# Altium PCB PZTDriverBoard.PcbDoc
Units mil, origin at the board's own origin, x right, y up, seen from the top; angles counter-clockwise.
Board outline 2900 x 7500 mil, 6 copper layers (Top Layer, GND1, P15, N15, GND2, Bottom Layer); 146 components, 71 nets, 417 pads, 78 vias.
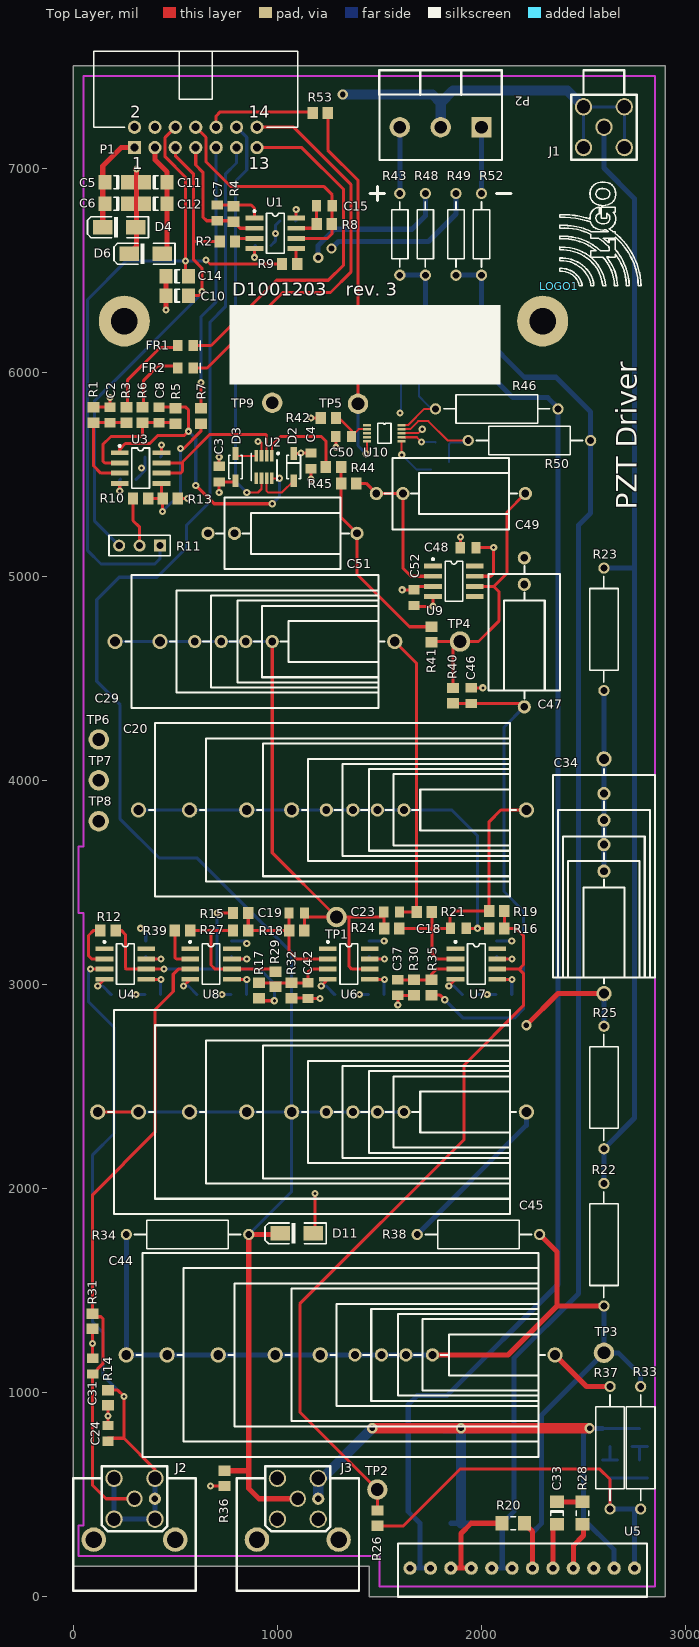
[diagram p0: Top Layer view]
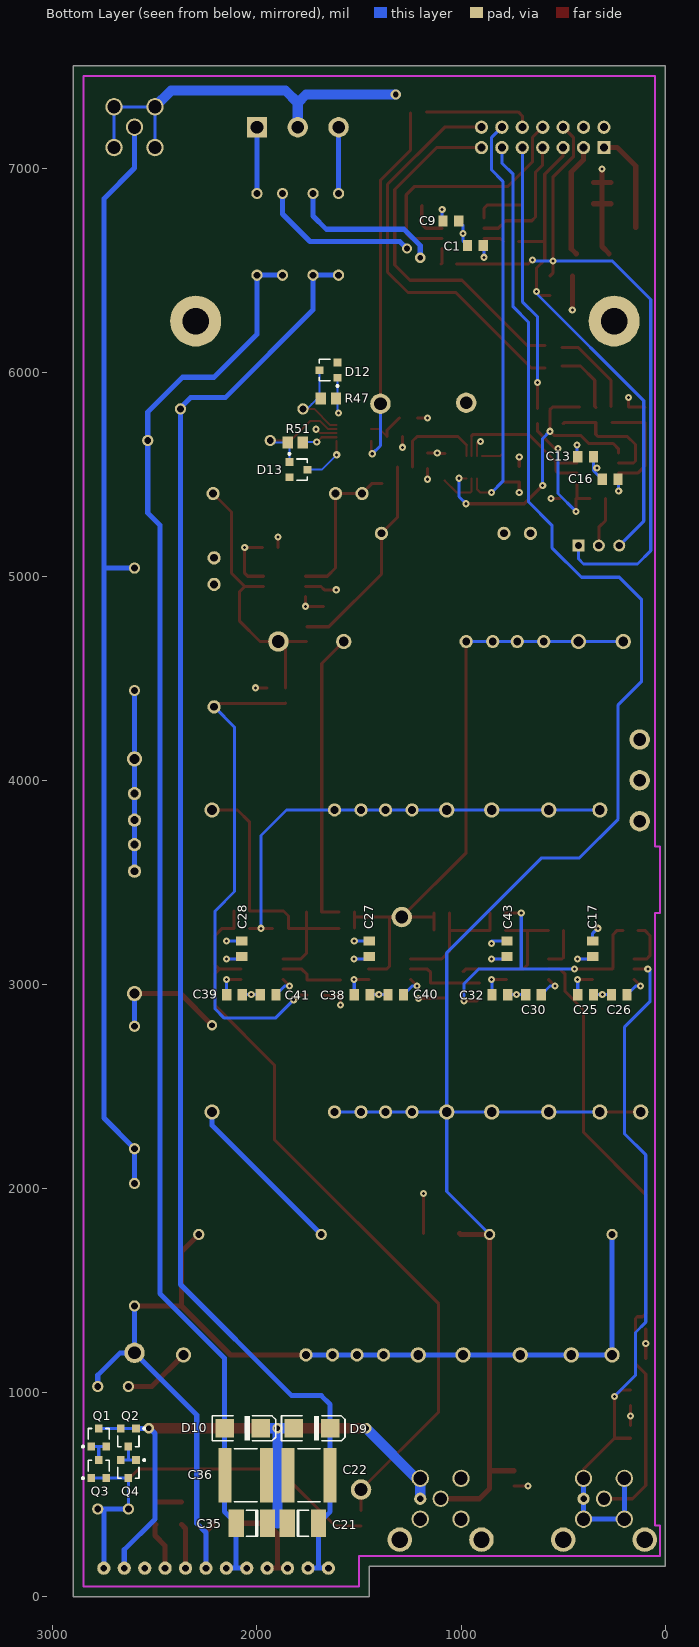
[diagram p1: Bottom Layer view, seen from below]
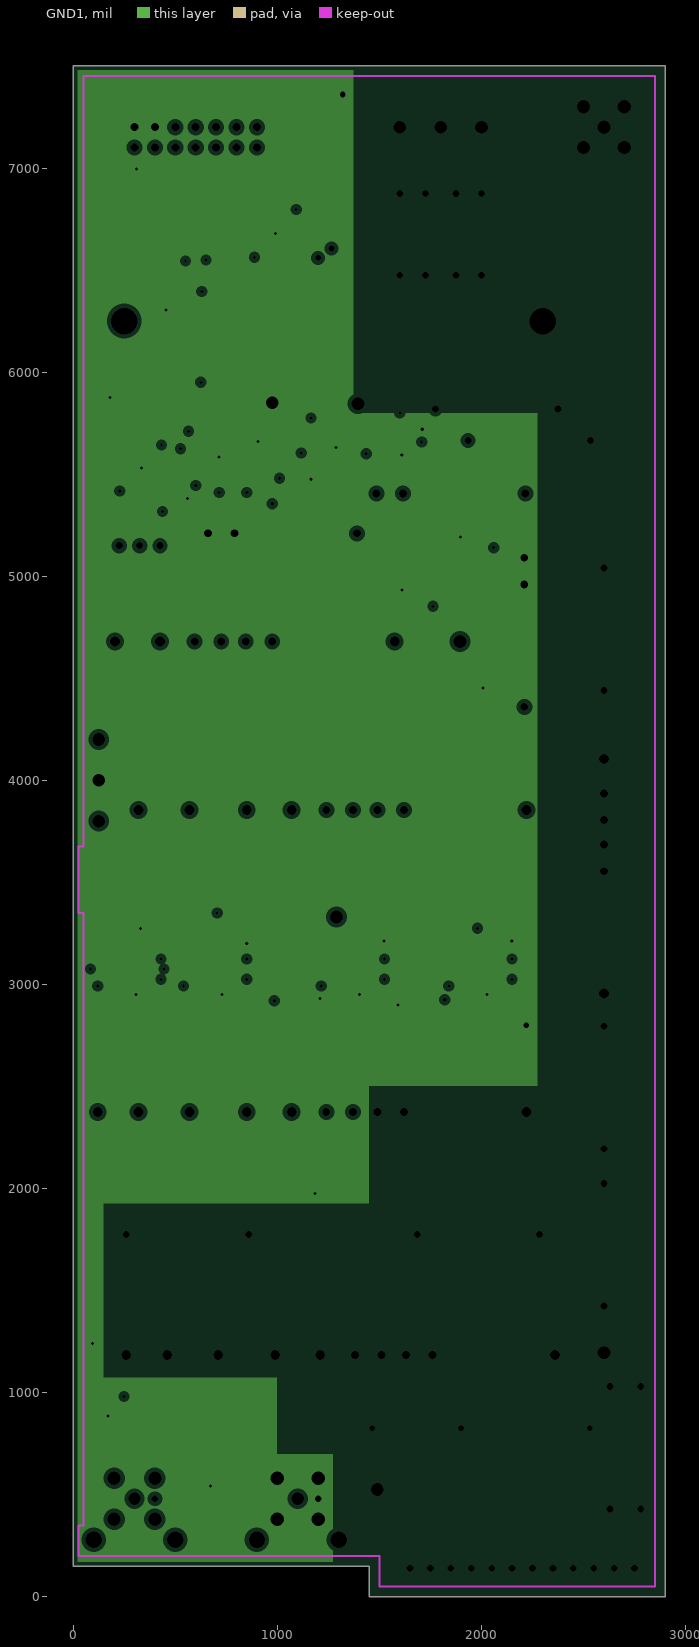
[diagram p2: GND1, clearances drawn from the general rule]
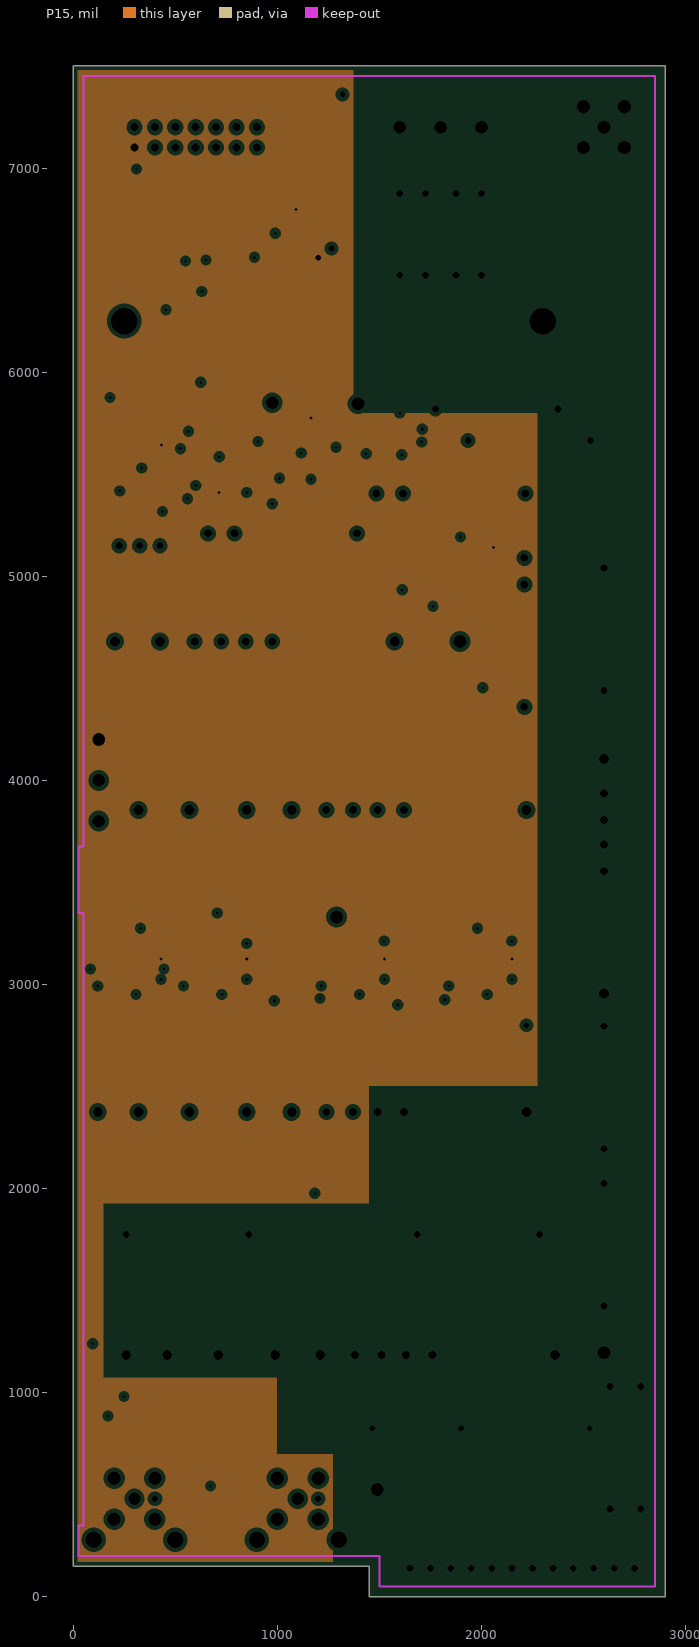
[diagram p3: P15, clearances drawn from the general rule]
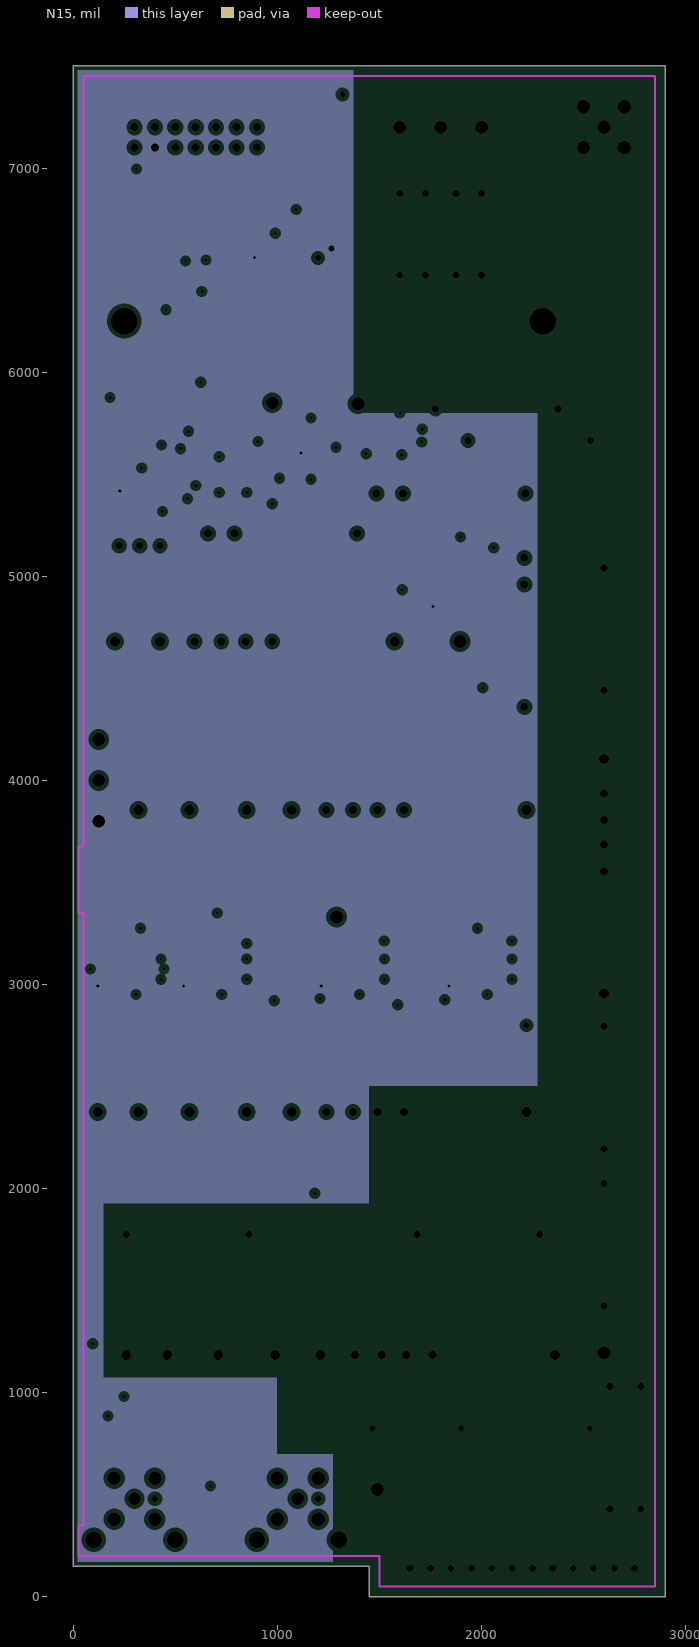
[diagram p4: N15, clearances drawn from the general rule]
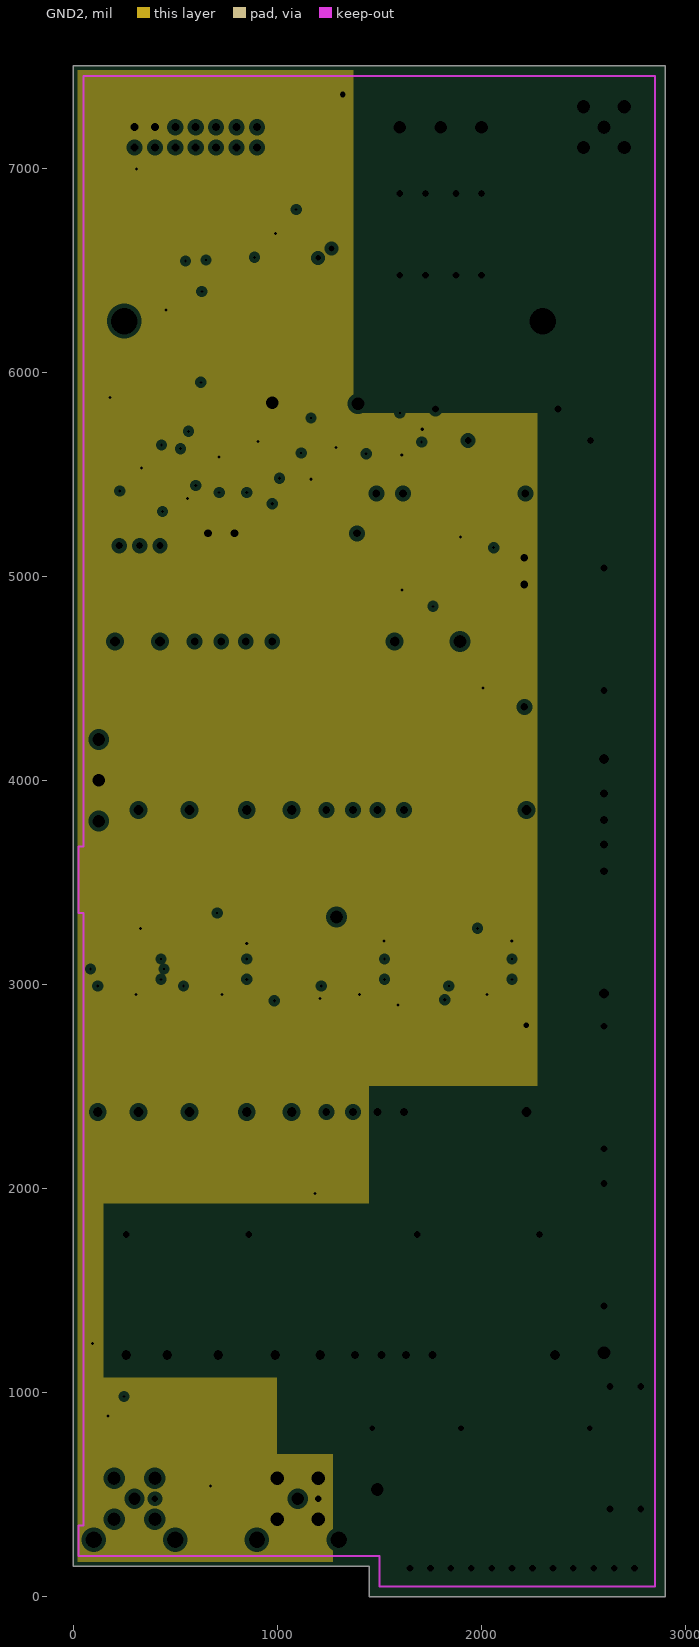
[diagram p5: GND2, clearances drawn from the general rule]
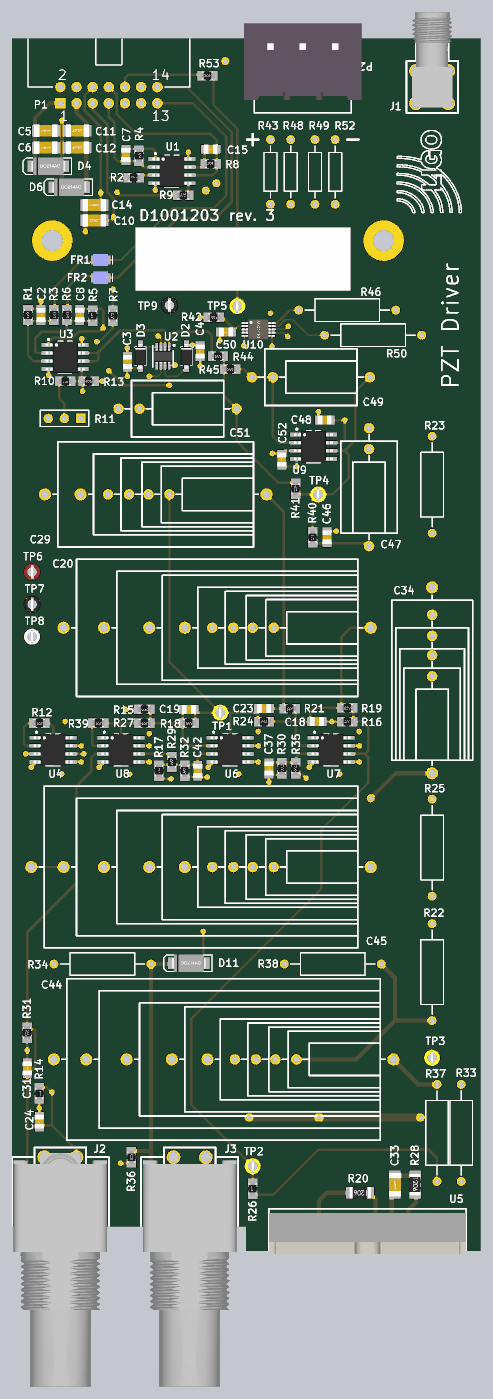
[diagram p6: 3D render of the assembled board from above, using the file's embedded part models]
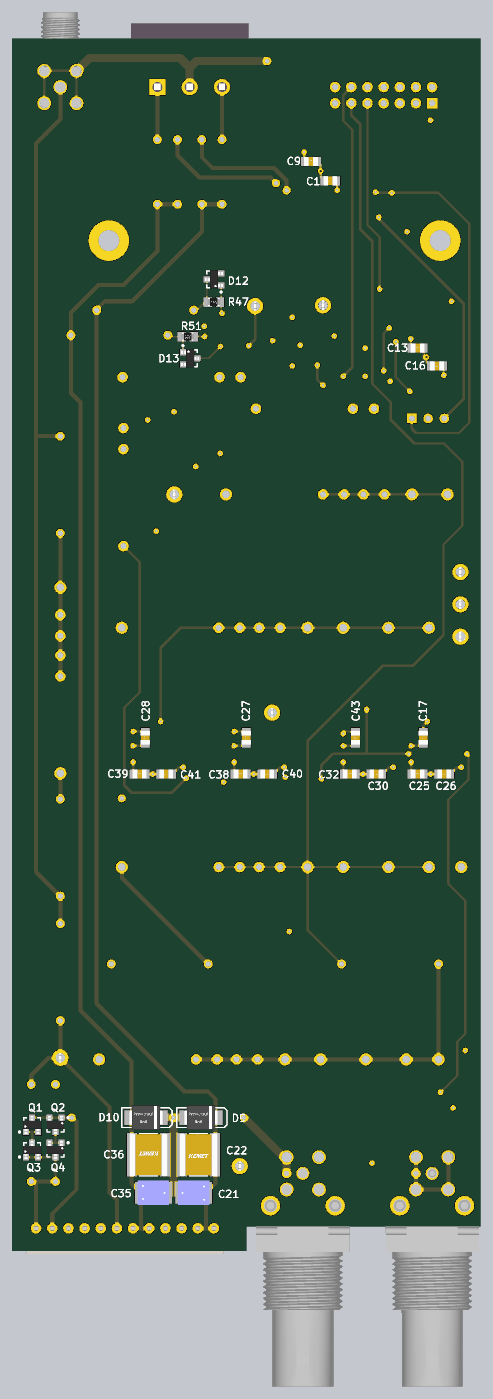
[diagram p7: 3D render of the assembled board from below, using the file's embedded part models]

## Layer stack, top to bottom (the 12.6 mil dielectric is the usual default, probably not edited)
Top Solder: solder mask 0.4, Solder Resist, Dk 3.5
Top Layer: signal copper 1.4
Dielectric1: core 12.6, FR-4, Dk 4.8
GND1: plane copper 1.4
Dielectric2: prepreg 12.6, FR-4, Dk 4.8
P15: plane copper 1.4
Dielectric3: core 12.6, FR-4, Dk 4.8
N15: plane copper 1.4
Dielectric4: prepreg 12.6, FR-4, Dk 4.8
GND2: plane copper 1.4
Dielectric5: core 12.6, FR-4, Dk 4.8
Bottom Layer: signal copper 1.4
Bottom Solder: solder mask 0.4, Solder Resist, Dk 3.5

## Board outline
0,150 0,7500 2900,7500 2900,0 1450,0 1450,150

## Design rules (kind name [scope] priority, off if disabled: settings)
Clearance Clearance_MSOP [(HasFootprint('MSOP10'))] p1: gap=8 ignorepadtopadclearanceinfootprint=FALSE
Clearance Clearance_HV [(InNet('N') OR InNet('P') OR InNet('PHV') OR InNet('NHV') OR InNet('HVFB') OR InNet('HVOUT'))] p2: gap=35 ignorepadtopadclearanceinfootprint=FALSE
Clearance [All] p3: gap=8 ignorepadtopadclearanceinfootprint=FALSE
Height [All] p1: minheight=0 maxheight=1200 prefheight=500
HoleSize [All] p1: absolutevalues=TRUE maxlimit=250 minlimit=15 maxpercent=80.000 minpercent=20.000
MinimumSolderMaskSliver [All] p1: minsoldermaskwidth=0
PlaneClearance [All] p1: clearance=20
PlaneConnect [All] p1: planeconnectstyle=Relief reliefexpansion=20 reliefentries=4 reliefconductorwidth=10 reliefairgap=10
PolygonConnect [All] p1: connectstyle=Relief reliefconductorwidth=10 reliefentries=4 polygonreliefangle="90 Angle" airgapwidth=10
RoutingVias [All] p1: holewidth=15 width=35 viastyle="Through Hole" minholewidth=15 minwidth=35 maxholewidth=28 maxwidth=50
SilkToSilkClearance [All] p1: silktosilkclearance=0
SilkToSolderMaskClearance SilkscreenOverComponentPads [IsPad] p1: minsilkscreentomaskgap=0 clearancetoexposedcopper=TRUE
SolderMaskExpansion [All] p1: expansion=4 istentingtop=FALSE
SupplyNets "Schematic Supply Nets_8" [InNet('VREF')] p1: voltage=0.000
SupplyNets "Schematic Supply Nets_7" [InNet('GND')] p2: voltage=0.000
SupplyNets "Schematic Supply Nets_6" [InNet('P15')] p3: voltage=0.000
SupplyNets "Schematic Supply Nets_5" [InNet('PHV')] p4: voltage=0.000
SupplyNets "Schematic Supply Nets_4" [InNet('NHV')] p5: voltage=0.000
SupplyNets "Schematic Supply Nets_3" [InNet('P')] p6: voltage=0.000
SupplyNets "Schematic Supply Nets_2" [InNet('N15')] p7: voltage=0.000
SupplyNets "Schematic Supply Nets_1" [InNet('N')] p8: voltage=0.000
SupplyNets "Schematic Supply Nets" [InNet('NREF')] p9: voltage=0.000
Width [All] p1: maxlimit=100 minlimit=8 preferedwidth=12
23 further rules are at their usual default settings.

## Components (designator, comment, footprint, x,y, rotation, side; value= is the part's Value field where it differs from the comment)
C1 "100n" CC2013-0805 930,6620 r180 bottom
C2 "1n" CC2013-0805 180,5790 r90 top
C3 "100n" CC2013-0805 715,5500 r270 top
C4 "100n" CC2013-0805 1165,5565 r270 top
C5 "100n" CC3216-1206 210,6930 r180 top
C6 "10u" CC3216-1206 210,6825 r180 top
C7 "1n" CC2013-0805 705,6780 r90 top
C8 "1n" CC2013-0805 420,5790 r90 top
C9 "100n" CC2013-0805 1050,6740 r0 bottom
C10 "100n" CC3216-1206 510,6375 r0 top
C11 "100n" CC3216-1206 405,6930 r0 top
C12 "10u" CC3216-1206 405,6825 r0 top
C13 "100n" CC2013-0805 390,5585 r0 bottom
C14 "100n" CC3216-1206 510,6470 r0 top
C15 "1n" CC2013-0805 1230,6815 r180 top
C16 "100n" CC2013-0805 270,5475 r180 bottom
C17 "100n" CC2013-0805 355,3175 r270 bottom
C18 "1n" CC2013-0805 1886.61,3275 r0 top
C19 "10p" CC2013-0805 1095,3350 r180 top
C20 "NL" CA-ALL8 2220,3855 r180 top
C21 "100n" CL4532-1812 1775,360 r180 bottom
C22 "1u" CC5664-2225 1745,595 r180 bottom
C23 "1n" CC2013-0805 1560,3355 r180 top
C24 "NL" CC2013-0805 170,800 r270 top
C25 "68p" CC2013-0805 390,2950 r0 bottom
C26 "100n" CC2013-0805 225,2950 r180 bottom
C27 "100n" CC2013-0805 1450,3175 r270 bottom
C28 "100n" CC2013-0805 2075,3175 r270 bottom
C29 "NL" CA-ALL6 1575,4680 r180 top
C30 "100n" CC2013-0805 645,2950 r180 bottom
C31 "NL" CC2013-0805 95,1130 r90 top
C32 "68p" CC2013-0805 810,2950 r0 bottom
C33 "68p" CC3216-1206 2370,410 r270 top
C34 "470n" CA-ALL5 2600,2955 r90 top value=270n
C35 "100n" CL4532-1812 2025,360 r0 bottom
C36 "1u" CC5664-2225 2055,595 r0 bottom
C37 "1n" CC2013-0805 1590,2985 r90 top
C38 "68p" CC2013-0805 1485,2950 r0 bottom
C39 "68p" CC2013-0805 2110,2950 r0 bottom
C40 "100n" CC2013-0805 1320,2950 r180 bottom
C41 "100n" CC2013-0805 1945,2950 r180 bottom
C42 "10p" CC2013-0805 1150,2970 r90 top
C43 "100n" CC2013-0805 775,3175 r270 bottom
C44 "1u" CA-ALL9 2360,1185 r180 top value=560n
C45 "1u" CA-ALL9 2220,2375 r180 top value=560n
C46 "1n" CC2013-0805 1950,4415 r90 top
C47 "1u" CA-ALL2 2210,4360 r90 top
C48 "100n" CC2013-0805 1935,5140 r0 top
C49 "330n" CA-ALL2 2215,5405 r180 top
C50 "100n" CC2013-0805 1325,5685 r0 top
C51 "1u" CA-ALL2 1390,5210 r180 top
C52 "100n" CC2013-0805 1670,4895 r270 top
D2 "DIODE" DO-SOD123 1080,5535 r90 top
D3 "DIODE" DO-SOD123 795,5535 r90 top
D4 "shottky diode" DO-SMA 225,6710 r180 top
D6 "shottky diode" DO-SMA 355,6580 r180 top
D9 "zener diode" DO-SMB 1730,825 r180 bottom
D10 "zener diode" DO-SMB 2070,825 r180 bottom
D11 "zener diode" DO-SMA 1095,1780 r180 top
D12 "Zener diode" SO-G3/C2.25 1650,6010 r90 bottom
D13 "Zener diode" SO-G3/C2.25 1797,5522 r270 bottom
FR1 "MPZ1608D300B" CL2013-0805 550,6130 r180 top
FR2 "MPZ1608D300B" CL2013-0805 550,6020 r180 top
J1 "SMA" SMA-RA 2600,7200 r180 top
J2 "SMA" SMA_BNC_VARIANT 300,20 r180 top
J2 "TNC" BNC_SMA 300,20 r180 top locked
J3 "BNC" BNC_SMA 1100,20 r180 top
LOGO1 "LIGO logo" LIGO_LOGO 2380,6420 r90 top
P1 "09 18 514 7323" 918514x323 600,7200 r0 top
P2 "TBlock_5.08_3" TBLOCK-5.08-3 1800,7200 r180 top
Q1 "MMBF4416A" SO-G3/C2.25 2775,780 r180 bottom
Q2 "MMBF4416A" SO-G3/C2.25 2630,780 r0 bottom
Q3 "MMBF4416A" SO-G3/C2.25 2775,625 r180 bottom
Q4 "MMBF4416A" SO-G3/C2.25 2630,625 r0 bottom
R1 "10K" CR2012-0805 100,5790 r90 top
R2 "4.99K" CR2012-0805 755,6640 r0 top
R3 "10K" CR2012-0805 260,5790 r270 top
R4 "100" CR2012-0805 785,6775 r270 top
R5 "10K" CR2012-0805 500,5785 r90 top
R6 "10K" CR2012-0805 340,5790 r270 top
R7 "49.9K" CR2012-0805 625,5785 r90 top
R8 "100" CR2012-0805 1230,6725 r0 top
R9 "4.99K" CR2012-0805 1060,6530 r0 top
R10 "49.9K" CR2012-0805 330,5380 r180 top
R11 "10K" HDR1X3 425,5150 r180 top
R12 "100" CR2012-0805 170,3265 r180 top
R13 "1M" CR2012-0805 475,5380 r180 top
R14 "1M" CR2012-0805 170,975 r270 top
R15 "4.99K" CR2012-0805 820,3350 r180 top
R16 "NL" CR2012-0805 2075,3275 r180 top
R17 "NL" CR2012-0805 910,2970 r270 top
R18 "4.99K" CR2012-0805 1095,3265 r180 top
R19 "4.99K" CR2012-0805 2075,3360 r180 top
R20 "20" CR3216-1206 2155,360 r180 top
R21 "NL" CR2012-0805 1720,3355 r180 top
R22 "499" AXIAL-0.6 2600,1725 r90 top
R23 "0" AXIAL-0.6 2600,4740 r90 top
R24 "4.99K" CR2012-0805 1560,3275 r180 top
R25 "NL" AXIAL-0.6 2600,2495 r270 top
R26 "12K" CR2012-0805 1490,385 r90 top
R27 "NL" CR2012-0805 820,3265 r180 top
R28 "100" CR3216-1206 2495,410 r270 top
R29 "4.99K" CR2012-0805 990,3025 r90 top
R30 "49.9K" CR2012-0805 1670,2985 r270 top
R31 "1M" CR2012-0805 95,1350 r90 top
R32 "4.99K" CR2012-0805 1070,2970 r90 top
R33 "150K" AXIAL-0.6 2780,730 r90 top value=240K
R34 "150K" AXIAL-0.6 560,1775 r0 top value=240K
R35 "0" CR2012-0805 1755,2985 r270 top
R36 "12K" CR2012-0805 740,580 r90 top
R37 "16.9K" AXIAL-0.6 2630,730 r90 top value=26.7K
R38 "16.9K" AXIAL-0.6 1985,1775 r180 top value=26.7K
R39 "100" CR2012-0805 535,3265 r180 top
R40 "49.9K" CR2012-0805 1860,4415 r270 top
R41 "49.9K" CR2012-0805 1755,4715 r270 top
R42 "10K" CR2012-0805 1250,5775 r180 top
R43 "0" AXIAL-0.4 1600,6675 r270 top
R44 "49.9K" CR2012-0805 1275,5535 r180 top
R45 "49.9K" CR2012-0805 1350,5455 r180 top
R46 "1M" AXIAL-0.6 2075,5820 r180 top
R47 "4.99K" CR2012-0805 1650,5870 r0 bottom value=2.94K
R48 "0" AXIAL-0.4 1725,6675 r270 top
R49 "0" AXIAL-0.4 1875,6675 r270 top
R50 "1M" AXIAL-0.6 2235,5665 r180 top
R51 "49.9K" CR2012-0805 1812,5656 r0 bottom value=4.99K
R52 "0" AXIAL-0.4 2000,6675 r270 top
R53 "0" CR2012-0805 1210,7270 r0 top
TP1 "Testpoint" TP1-YLW 1290,3330 r0 top
TP2 "Testpoint" TP1-YLW 1490,525 r0 top
TP3 "Testpoint" TP1-YLW 2600,1195 r0 top
TP4 "Testpoint" TP1-YLW 1895,4680 r0 top
TP5 "Testpoint" TP1-YLW 1395,5845 r0 top
TP6 "Testpoint" TP1-RED 125,4200 r0 top
TP7 "Testpoint" TP1-BLK 125,4000 r0 top
TP8 "Testpoint" TP1-WHT 125,3800 r0 top
TP9 "Testpoint" TP1-BLK 975,5850 r0 top
U1 "AD8672AR" SO-G8 990,6680 r270 top
U2 "MAX4649" SSO-G8/NARROW 935,5535 r180 top
U3 "AD8672AR" SO-G8 330,5530 r270 top
U4 "AD829JR" SO-G8 255,3100 r270 top
U5 "PA90" PA98 2750,140 r180 top locked
U6 "AD829JR" SO-G8 1350,3100 r270 top
U7 "AD829JR" SO-G8 1975,3100 r270 top
U8 "AD829JR" SO-G8 675,3100 r270 top
U9 "OP27" SO-G8 1865,4975 r270 top
U10 "LTC2919" MSOP10 1440,5740 r0 top

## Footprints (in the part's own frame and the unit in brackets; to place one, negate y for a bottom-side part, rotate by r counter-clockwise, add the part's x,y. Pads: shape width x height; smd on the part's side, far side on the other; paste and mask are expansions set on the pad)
918514x323 [mm] "Connector; IDC, Low Profile Male Header, Thru-Hole; 14 Position; Right Angle; Pitch 2.54 mm; Body 25.40 x 8.9 x 9.2 mm (LxWxH)"
  rect 1.65x1.65 hole 1: 1(-7.62,-2.54)
  round 1.65 hole 1: 2(-7.62,0) 3(-5.08,-2.54) 4(-5.08,0) 5(-2.54,-2.54) 6(-2.54,0) 7(0,-2.54) 8(0,0) 9(2.54,-2.54) 10(2.54,0) 11(5.08,-2.54) 12(5.08,0) 13(7.62,-2.54) 14(7.62,0)
  silkscreen extent -12.7,0 12.7,9.45
AXIAL-0.4 [mm] "Axial Device, Thru-Hole; 2 Leads; 0.4 in Pin Spacing"
  round 1.4 hole 0.85: 1(-5.08,0) 2(5.08,0)
  silkscreen extent -4.06,-1.02 4.06,1.02, body extent -3.05,-1.14 3.05,1.14, height 2.35
AXIAL-0.6 [mm] "Axial Device, Thru-Hole; 2 Leads; 0.6 in Pin Spacing"
  round 1.4 hole 0.85: 1(-7.62,0) 2(7.62,0)
  silkscreen extent -6.6,-1.78 6.6,1.78, body extent -5.08,-1.83 5.08,1.83, height 3.73
BNC_SMA [mil] "BNC right angle PCB with alternative SMA footprint"
  round 80 hole 60: 1(0,-460)
  round 85 hole 65: 2(-100,-360) 2(-100,-560) 2(100,-360) 2(100,-560)
  round 60 hole 32: 2(-100,-460)
  round 120 hole 80: 3(-200,-260) 4(200,-260)
  silkscreen extent -300,-620 300,-10, body extent -289,-540 289,858, height 623
CA-ALL2 [mil] "Axial film capacitor, Size up to 0.53\"(L) x 0.35\"(D)"
  round 65 hole 38: 1(0,0) 2(600,0) 2(730,0)
  silkscreen extent 40,-175 690,175, body extent 80,-175 650,175, height 360
CA-ALL5 [mil] "Axial film capacitor, Size up to 0.95\"(L) x 0.5\"(D)"
  round 75 hole 48: 1(0,0) 2(1150,0)
  round 65 hole 38: 2(600,0) 2(730,0) 2(850,0) 2(980,0)
  silkscreen extent 50,-250 1100,250, body extent 80,-250 1070,250, height 510
CA-ALL6 [mil] "Axial film capacitor, Size up to 1.17\"(L) x 0.65\"(D)"
  round 75 hole 48: 1(0,0) 2(1150,0) 2(1370,0)
  round 65 hole 38: 2(600,0) 2(730,0) 2(850,0) 2(980,0)
  silkscreen extent 50,-325 1320,325, body extent 80,-325 1290,325, height 660
CA-ALL8 [mil] "Axial film capacitor, Size up to 1.68\"(L) x 0.85\"(D)"
  round 75 hole 48: 1(0,0) 2(1150,0) 2(1370,0) 2(1650,0) 2(1900,0)
  round 65 hole 38: 2(600,0) 2(730,0) 2(850,0) 2(980,0)
  silkscreen extent 50,-425 1850,425, body extent 80,-425 1820,425, height 860
CA-ALL9 [mil] "Axial film capacitor, Size up to 1.9\"(L) x 1.0\"(D)"
  round 75 hole 48: 1(0,0) 2(1150,0) 2(1370,0) 2(1650,0) 2(1900,0) 2(2100,0)
  round 65 hole 38: 2(600,0) 2(730,0) 2(850,0) 2(980,0)
  silkscreen extent 50,-500 2050,500, body extent 80,-500 2020,500, height 1010
CC2013-0805 [mm] "Chip Capacitor; Body 2.0 x 1.3 mm (LxW typ)"
  rect 1.15x1.4 smd: 1(-0.975,0) 2(0.975,0)
  body extent -1.1,-0.73 1.1,0.72, height 0.88
CC3216-1206 [mm] "Chip Capacitor; Body 3.2 x 1.6 mm (LxW typ)"
  rect 1.6x1.8 smd: 1(-1.4,0) 2(1.4,0)
  silkscreen extent -0.3,-0.8 0.3,0.8, body extent -1.85,-0.97 1.85,0.97, height 0.88
CC5664-2225 [mm] "Chip Capacitor, Body 5.6 x 6.4mm (LxW typ)"
  rect 1.6x6.8 smd: 1(-2.6,0) 2(2.6,0)
  silkscreen extent -1.4,-3.3 1.4,3.3, body extent -3,-3.4 3,3.4, height 1.55
CL2013-0805 [mm] "Chip Inductor; Body 2.0 x 1.3 mm (LxW typ)"
  rect 1.15x1.4 smd: 1(-0.975,0) 2(0.975,0)
  silkscreen extent -1.85,-0.6 -1.85,0.6, body extent -1.15,-0.95 1.14,0.96, height 1.59
CL4532-1812 [mm] "Chip Inductor; Body 4.5 x 3.2 mm (LxW typ)"
  rect 1.9x3.4 smd: 1(-1.95,0) 2(1.95,0)
  silkscreen extent -0.7,-1.6 0.7,1.6, body extent -2.47,-1.91 2.47,1.91, height 3.42
CR2012-0805 [mm] "Chip Resistor; Body 2.0 x 1.3 mm (LxW typ)"
  rect 1.3x1.5 smd: 1(-0.95,0) 2(0.95,0)
  body extent -1,-0.62 1,0.63, height 0.46
CR3216-1206 [mm] "Chip Resistor; Body 3.2 x 1.6 mm (LxW typ)"
  rect 1.6x1.8 smd: 1(-1.4,0) 2(1.4,0)
  silkscreen extent -0.3,-0.8 0.3,0.8, body extent -1.67,-0.86 1.68,0.87, height 0.85
DO-SMA [mm] "DO-214-AC/SMA; 2 C-Bend Leads; Body 5 x 2.7 mm, inc. leads (LxW)"
  rect 2.4x1.8 smd: 1(-2.05,0) 2(2.05,0)
  silkscreen extent -3.65,-1.3 3.95,1.3, body extent -2.74,-1.4 2.74,1.4, height 2.41
DO-SMB [mm] "DO-214-AA/SMB; 2 C-Bend Leads; Body 5.3 x 3.6 mm, inc. leads (LxW)"
  rect 2.3x2.3 smd: 1(-2.25,0) 2(2.25,0)
  silkscreen extent -3.8,-1.55 4.1,1.55, body extent -2.75,-1.95 2.75,1.95, height 2.45
DO-SOD123 [mm] "SOD-123; 2 Leads; Body 2.7 x 1.6 mm, (LxW)"
  rect 1.6x0.8 smd: 1(-1.7,0) 2(1.7,0)
  silkscreen extent -1.45,-0.85 1.45,0.85, body extent -1.95,-0.9 1.95,0.9, height 1.18
HDR1X3 [mm] "Connector; Header; 3 Position"
  rect 1.5x1.5 hole 0.9: 1(0,0)
  round 1.5 hole 0.9: 2(2.54,0) 3(5.08,0)
  silkscreen extent -1.27,-1.27 6.35,1.27
LIGO_LOGO [mil] "LIGO logo"
  silkscreen extent 3,-402 511,-3
MSOP10 [mm] "MSOP Plastic Small-Outline Package"
  rect 1x0.297 smd: 1(0,0) 2(0,-0.5) 3(0,-1) 4(0,-1.5) 5(0,-2) 6(4.3,-2) 7(4.3,-1.5) 8(4.3,-1) 9(4.3,-0.5) 10(4.3,0)
  silkscreen extent 1.33,-2.25 2.97,0.25, body extent -0.44,-2.59 4.71,0.61, height 1.09
PA98 [mil] "12-pin SIP package"
  round 65 hole 33: 1(0,0) 2(100,0) 3(200,0) 4(300,0) 5(400,0) 6(500,0) 7(600,0) 8(700,0) 9(800,0) 10(900,0) 11(1000,0) 12(1100,0)
  silkscreen extent -60,-120 1160,140, body extent -60,-95 1160,158, height 1017
SMA-RA [mil] "SMA right angle PCB"
  round 85 hole 65: 1(0,0) 2(-100,100) 2(-100,-100) 2(100,100) 2(100,-100)
  silkscreen extent -160,-160 160,160, body extent -125,-460 125,125, height 375
SMA_BNC_VARIANT [mil] "SMA straight PCB with alternative BNC footprint (3D-body only)"
  body extent -126,-586 126,-334, height 370
SO-G3/C2.25 [mm] "SOT-23; 3 Leads; Body 3.0 x 2.5 mm, inc. leads (LxW max)"
  rect 0.95x1 smd: 1(-0.95,-1.125) 2(0.95,-1.125) 3(0,1.125)
  silkscreen extent -2.1,-1.25 1.32,1.13, body extent -1.45,-1.4 1.45,1.4, height 1.3
SO-G8 [mm] "Small Outline; 8 Leads; Body Width 3.9 mm; Pitch 1.27 mm"
  rect 0.6x2.2 smd: 1(-1.905,-2.6) 2(-0.635,-2.6) 3(0.635,-2.6) 4(1.905,-2.6) 5(1.905,2.6) 6(0.635,2.6) 7(-0.635,2.6) 8(-1.905,2.6)
  silkscreen extent -2.88,-2.72 2.5,1.1, body extent -2.47,-3.06 2.47,3.06, height 1.75
SSO-G8/NARROW [mm] "SSOP narrow; 8 Leads; Body Width 1.7 mm; Pitch 0.65 mm"
  rect 0.445x1.4 smd: 1(-0.975,-1.4) 2(-0.325,-1.4) 3(0.325,-1.4) 4(0.975,-1.4) 5(0.975,1.4) 6(0.325,1.4) 7(-0.325,1.4) 8(-0.975,1.4)
  silkscreen extent -1.88,-1.82 1.6,1.7, body extent -1.5,-1.5 1.5,1.5, height 1.45
TBLOCK-5.08-3 [mil] "Terminal Block, 5.08mm, 3pin"
  rect 100x100 hole 62: 1(-200,0)
  round 100 hole 62: 2(0,0) 3(200,0)
  silkscreen extent -300,-160 300,160, body extent -363,-393 363,80, height 334
TP1-BLK [mm] "Testpoint pin, black"
  round 2.54 hole 1.58: 1(0,0)
  body extent -1.27,-1.27 1.27,1.27, height 4.89
TP1-RED [mm] "Testpoint pin, red"
  round 2.54 hole 1.58: 1(0,0)
  body extent -1.27,-1.27 1.27,1.27, height 4.89
TP1-WHT [mm] "Testpoint pin, white"
  round 2.54 hole 1.58: 1(0,0)
  body extent -1.27,-1.27 1.27,1.27, height 4.89
TP1-YLW [mm] "Testpoint pin, yellow"
  round 2.54 hole 1.58: 1(0,0)
  body extent -1.27,-1.27 1.27,1.27, height 4.89

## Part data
C1 C3 C4 C9 C13 C16 C17 C26 C27 C28 C30 C40 C41 C43 C48 C50 C52: library part ChipCap, "Capacitor, surface mount", Part Number=311-1140-1-ND, Tolerance=10%
C2 C7 C8 C15 C18 C23 C37 C46: library part ChipCap, "Capacitor, surface mount", Part Number=399-C0805C102J5GACTUCT-ND, Tolerance=10%
C5 C10 C11 C14: library part ChipCap, "Capacitor, surface mount", Part Number=311-1179-1-ND, Tolerance=10%
C6 C12: library part ChipCap, "Capacitor, surface mount", Part Number=1276-6767-1-ND, Tolerance=10%
C19 C42: library part ChipCap, "Capacitor, surface mount", Part Number=311-1099-1-ND, Tolerance=10%
C20 C29: library part CapFilmAxial, "Film Capacitor, axial lead", Tolerance=1%, Voltage Rating=50V
C21 C35: library part ChipCap, "Capacitor, surface mount", Part Number=490-16695-1-ND, Tolerance=10%, Voltage Rating=630V
C22 C36: library part ChipCap, "Capacitor, surface mount", Part Number=490-GRM43DR7LV224KW01LCT-ND, Tolerance=10%, Voltage Rating=630V
C24 C31: library part ChipCap, "Capacitor, surface mount", Tolerance=10%
C25 C32 C38 C39: library part ChipCap, "Capacitor, surface mount", Part Number=311-1109-1-ND, Tolerance=10%
C33: library part ChipCap, "Capacitor, surface mount", Part Number=490-4300-1-ND, Tolerance=10%, Voltage Rating=630V
C34: library part CapFilmAxial, "Film Capacitor, axial lead", Part Number=P12243-ND, Tolerance=5%, Voltage Rating=630V
C44 C45: library part CapFilmAxial, "Film Capacitor, axial lead", Part Number=2870-MKP1839456634HQ-ND, Tolerance=1%, Voltage Rating=630V
C47 C51: library part CapFilmAxial, "Film Capacitor, axial lead", Part Number=MU12B105F, Supplier Part Number 1=PCF1616-ND, Tolerance=1%, Voltage Rating=50V
C49: library part CapFilmAxial, "Film Capacitor, axial lead", Part Number=MU12B334F, Supplier Part Number 1=P122561-ND, Tolerance=1%, Voltage Rating=50V
D2 D3: "Single diode", Part Number=B0530W-FDICT-ND, Voltage Rating=30V
D4 D6: library part DIODE_SHOTTKY, "Single shottky diode", Part Number=641-1702-1-ND, Voltage Rating=40V
D9: library part DIODE_ZENER, "Single zener diode", Part Number=SMBJ200ALFCT-ND, Voltage Rating=200V
D10: library part DIODE_ZENER, "Single zener diode", Part Number=SMBJ120ALFCT-ND, Voltage Rating=120V
D11: library part DIODE_ZENER, "TVS", Part Number=576-SMAJ20CA, Voltage Rating=20V
D12 D13: library part DIODE_ZENER_SOT23, "Single zener diode in SOT23 package", Part Number=MMBZ5229BLT1GOSCT-ND, Voltage Rating=4.3V
FR1 FR2: library part BLM31PG121SN1, "ferrite bead, 20Ohm at 1GHz, 603", Part Number=490-1041-1-ND
J1: "SMA, PCB Mount, Right Angle", Part Number=ARF1206-ND
J2: library part BNC_SMA_VARIANT, "BNC, PCB Mount, Right Angle"
J2: library part BNC, "BNC, PCB Mount, Right Angle", Part Number=WM9356-ND
J3: "BNC, PCB Mount, Right Angle", Part Number=A32258-ND
LOGO1: library part LIGO_logo
P1: "Flat Cable Connector (IDC), Low-Profile Male Header, Angled Solder Pin, 14 Contacts, Performance Level 3", Part Number=A31177-ND
P2: "Terminal block, 5.08mm, 3-Pin", Part Number=1148070000-ND
Q1 Q2 Q3 Q4: library part PMBF4416A, "N-channel Silicon Junction Field-effect Transistor", Part Number=512-MMBF4416A
R1 R3 R5 R6 R42: library part ChipRes1, "Resistor, surface mount", Part Number=P10KDACT-ND, Tolerance=0.1%
R2 R9 R15 R18 R19 R24 R29 R32 R51: library part ChipRes1, "Resistor, surface mount", Part Number=P4.99KDACT-ND, Tolerance=0.1%
R4 R8 R12 R39: library part ChipRes1, "Resistor, surface mount", Part Number=P100DACT-ND, Tolerance=0.1%
R7 R10 R30 R40 R41 R44 R45: library part ChipRes1, "Resistor, surface mount", Part Number=P49.9KDACT-ND, Tolerance=0.1%
R11: library part RPot2, "Potentiometer", Part Number=118-3296W-1-103ALFCT-ND
R13 R14 R31: library part ChipRes1, "Resistor, surface mount", Part Number=P1MDACT-ND, Tolerance=0.1%
R16 R17 R21 R27: library part ChipRes1, "Resistor, surface mount", Tolerance=0.1%
R20: library part ChipRes1, "Resistor, surface mount", Part Number=311-20.0FRCT-ND, Tolerance=1%
R22 R25: library part Res2, "Resistor", Part Number=PPC499ZCT-ND, Power Rating=0.5W, Tolerance=1%, Voltage Rating=350V
R23: library part Res2, "Resistor", Part Number=JW60ZT0R00CT-ND, Power Rating=0.5W, Tolerance=1%, Voltage Rating=350V
R26 R36: library part ChipRes1, "Resistor, surface mount", Part Number=P12KDACT-ND, Tolerance=0.5%
R28: library part ChipRes1, "Resistor, surface mount", Part Number=311-100FRCT-ND, Tolerance=1%
R33 R34: library part Res2, "Resistor", Part Number=279-LR1F240K, Power Rating=0.5W, Tolerance=1%, Voltage Rating=350V
R35 R53: library part ChipRes1, "Resistor, surface mount", Part Number=541-0.0ACT-ND, Tolerance=0.1%
R37 R38: library part Res2, "Resistor", Part Number=PPC26.7KZCT-ND, Power Rating=0.5W, Tolerance=1%, Voltage Rating=350V
R43 R48 R49 R52: library part Res2, "Resistor", Part Number=JW60ZT0R00CT-ND
R46 R50: library part Res2, "Resistor", Part Number=PPCQF1.0MCT-ND, Power Rating=0.25W, Tolerance=1%, Voltage Rating=350V
R47: library part ChipRes1, "Resistor, surface mount", Part Number=P2.94KDACT-ND, Tolerance=0.1%
TP1 TP2 TP3 TP4 TP5: library part TP_SIGNAL, "Testpoint, yellow", Part Number=36-5009-ND
TP6: library part TP_POSITIVE, "Testpoint, red", Part Number=36-5005-ND
TP7 TP9: library part TP_GND, "Testpoint, black", Part Number=36-5006-ND
TP8: library part TP_NEGATIVE, "Testpoint, white", Part Number=36-5007-ND
U1 U3: library part OP285GS, "Dual, 9MHz Precision Operational Amplifier", Part Number=505-AD8672ARZ-REELCT-ND
U2: "Single SPDT analog switch", Part Number=MAX4649EKA+TCT-ND
U4 U6 U7 U8: "High-Speed, Low-Noise Video Operational Amplifier", Part Number=505-AD829ARZ-REELCT-ND
U5: library part PA98, "Socket 12 pin for HV Power Op Amp", Part Number=ED4864-12-ND
U9: library part AD829JR, "High-Speed, Low-Noise Video Operational Amplifier", Part Number=OP27GSZ-REEL7CT-ND
U10: "Precision Triple/Dual Input UV, OV and Negative Voltage Monitor", Part Number=LTC2919CMS-5#PBF-ND

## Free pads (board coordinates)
  round 250 hole 130: 0(250,6250) 0(2300,6250)

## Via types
v1: diameter 35, hole 15, Top Layer to Bottom Layer, 71 vias
v2: diameter 50, hole 28, Top Layer to Bottom Layer, 7 vias

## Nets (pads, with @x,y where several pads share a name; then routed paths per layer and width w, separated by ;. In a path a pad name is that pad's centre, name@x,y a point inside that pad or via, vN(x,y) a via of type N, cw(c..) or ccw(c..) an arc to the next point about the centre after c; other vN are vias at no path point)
EXT: P1.12 U2.6 | length 1988.3
  Top Layer w10: v1(850,5410) 905,5410 922.2,5427.2 U2.6
  Bottom Layer w15: P1.12 850,7150 850,6990 795,6935 795,5465 v1(850,5410)
GND: C1.1 C2.2 C3.1 C4.2 C5.1 C6.1 C9.1 C10.1 C11.1 C12.1 C13.1 C14.1 C16.1 C17.1 C21.1 C22.1 C24.1 C25.1 C26.1 C27.1 C28.1 C30.1 C31.2 C32.1 C34.1 C35.1 C36.1 C37.1 C38.1 C39.1 C40.1 C41.1 C42.1 C43.1 C46.2 C47.2 C48.1 C50.1 C51.2 C52.1 D4.1 D6.2 D9.1 D10.2 D11.1 D12.1 D13.3 J1.2 J3.2 P1.2 P1.4 P2.2 Q1.3 Q2.1 Q2.2 R1.2 R13.1 R14.2 R25.1 R30.2 R31.1 R32.1 R36.1 R47.1 TP7.1 TP9.1 U2.3 U5.2 U9.3 U10.6 U10.8 | length 9505.1
  Top Layer w10: v1(905,5660) 915,5660 922.2,5652.8 U2.3 ; v1(1609.29,5595) U10.6 ; U10.8 1690.63,5700.63 v1(1710,5720)
  Top Layer w15: C31.2 v1(95,1240) ; R31.1 v1(95,1240) ; v1@100,1240 v1(95,1240) ; R1.2 100.98,5828.39 C2.2 v1(180,5875) ; C24.1 R14.2 ; R13.1 v1(560,5380) ; v1(672.4,542.6) R36.1 ; C3.1 v1(715,5585) ; R32.1 C42.1@1149.02,2932.6 ; C42.1 v1(1208.39,2931.61) ; v1(1165,5475) C4.2 ; D11.1@1183.58,1780 v1(1183.58,1976.42) ; v1(1286.61,5631.61) C50.1 ; v1(1590,2900) C37.1 1669.02,2946.61 R30.2 ; v1(1611.61,4933.39) C52.1 1686.61,4950 U9.3 ; C48.1 v1(1896.61,5191.61) ; C46.2 v1(2006.61,4453.39)
  Top Layer w25: C6.1 310,6825 ; C5.1 310,6930 ; D6.2 310,6615.71 310,6825 ; v1(310,6995) 310,6930 ; C12.1 310,6825 ; C11.1 310,6930 ; v1(454.88,6305.12) C14.1 ; v2(2220,2800) 2375,2955 C34.1 ; 310,6825 310,6930
  Top Layer w50: v2(1465,825) v2(1900,825) v2(2530,825)
  Bottom Layer w10: v1(1600,5800) 1600,5806.76 1605.71,5812.47 D12.1 ; v1(1609.29,5595) 1682.29,5522 D13.3
  Bottom Layer w15: C26.1 v1(308,2950) C25.1 ; C16.1 349.19,5515.81 ; v1(330,3275) 355,3250 C17.1 ; v1(335,5530) v1@351.61,5530 ; 351.61,5518.23 v1@351.61,5530 ; C13.1 v1@351.61,5530 ; C30.1 v1(728,2950) C32.1 ; C43.1 848.39,3213.39 850,3211.77 v1(850,3200) ; C1.1 990,6641.61 990,6718.39 C9.1 ; C40.1 v1(1403,2950) C38.1 ; C27.1 v1(1523.39,3213.39) ; C41.1 v1(2028,2950) C39.1 ; C28.1 v1(2148.39,3213.39) ; J1.2@2500,7100 2500,7300 2700,7300 J1.2@2700,7100 ; Q2.1 Q1.3
  Bottom Layer w25: C21.1 1900,360 C35.1 ; Q2.1 2524.29,824.29 2500,800 2500,380 2650,230 U5.2 ; R25.1@2595,2795 2600,2800 C34.1
  Bottom Layer w50: J3.2@1200,480 1200,560 v2(1465,825) ; v2(1320,7360) 1760,7360 1800,7320 ; P2.2 1800,7320 ; D9.1 v2(1900,825) D10.2 ; 1900,360 v2@1900,820 ; J1.2@2500,7300 2420,7380 1860,7380 1800,7320
  other v1: 170,885 990,6680
HVFB: C44.2 R20.1 R22.1 R33.2 R34.1 R38.1 TP3.1 U5.6 | length 5361.7
  Top Layer w25: C44.2@1760,1185 2130,1185 2370,1425 ; R20.1 2250,320.12 U5.6 ; R38.1 2370,1690 2370,1425 ; R22.1 2370,1425
  Bottom Layer w25: R34.1 260,1185 460,1185 710,1185 990,1185 1210,1185 1380,1185 1510,1185 1630,1185 C44.2@1760,1185 ; U5.6 2250,315 2295,360 2295,890 TP3.1 ; R22.1 TP3.1 ; R33.2 2780,1085 2670,1195 TP3.1
HVOUT: J1.1 R22.2 R23.2 R25.2 | length 5449.3
  Bottom Layer w25: R22.2 R25.2 2750,2345 2750,4400 2750,6850 2600,7000 J1.1 ; R23.2 2750,5040
MON: C45.2 D11.2 J3.1 P1.11 R34.2 R36.2 | length 9583.3
  Top Layer w15: C45.2@120,2375 C45.2@320,2375 ; 857.4,617.4 860,620
  Top Layer w25: R36.2 857.4,617.4 ; D11.2@1006.42,1780 1001.42,1775 R34.2 860,620.1 860,530 910,480 J3.1
  Bottom Layer w15: C45.2@320,2375 570,2375 850,2375 C45.2@1070,2375 ; P1.11 800,7025 745,6970 745,6320 670,6245 670,5365 555,5250 555,5140 410,4995 225,4995 115,4885 115,4485 230,4370 230,3810 420,3620 605,3620 1070,3155 C45.2@1070,2375 ; R34.2 1070,1985 C45.2@1070,2375 ; C45.2@1620,2375 1490,2375 1370,2375 1240,2375 C45.2@1070,2375
N: C35.2 C36.2 D10.1 R49.2 R50.1 R52.2 U5.7 U5.8 | length 7052.6
  Bottom Layer w25: R49.2 R52.2 2000,6185 2210,5975 2365,5975 2535,5805 2535,5655 2535,5310 2475,5250 2475,1485 2158.58,1168.58 D10.1 2158.58,416.81 C35.2 2101.77,141.77 2100,140 ; U5.8 2100,140 ; U5.7 2100,140
N15: C1.2 C4.1 C11.2 C12.2 C16.2 C26.2 C30.2 C40.2 C41.2 C52.2 D2.2 D6.1 P1.3 R49.1 TP8.1 U1.4 U3.4 U4.4 U6.4 U7.4 U8.4 U9.4 | length 2274.3
  Top Layer w15: v1(120,2992.36) U4.4 ; v1(227.64,5417.36) U3.4 ; v1(540,2992.36) U8.4 ; v1(887.64,6562.64) U1.4 ; D2.2 v1@1115.16,5601.93 ; v1(1116.61,5603.39) C4.1 ; v1(1215,2992.36) U6.4 ; C52.2@1673.98,4852.64 v1(1762.64,4852.64) U9.4 ; v1(1840,2992.36) U7.4
  Top Layer w25: P1.3 400,7040 460.12,6979.88 C11.2 C12.2 460.12,6604.41 D6.1
  Bottom Layer w15: v1(120,2992.36) 144.25,2992.36 C26.2 ; v1(227.64,5417.36) 227.64,5471.02 C16.2 ; v1(540,2992.36) 564.25,2992.36 C30.2 ; v1(887.64,6562.64) 887.64,6616.02 C1.2 ; v1(1215,2992.36) 1239.25,2992.36 C40.2 ; v1(1840,2992.36) 1864.25,2992.36 C41.2
  Bottom Layer w25: v2(1265.19,6605.19) 1300,6640 1740,6640 1875,6775 R49.1
NB: C15.1 P1.8 R8.2 U1.6 | length 1251.7
  Top Layer w15: P1.8 650,7150 650,7030 770,6910 1226.77,6910 1268.39,6868.39 C15.1 1268.39,6725.98 R8.2 1267.4,6677.4 1245,6655 U1.6
NetC2_1: C2.1 R1.1 R3.2 U3.3 | length 514.7
  Top Layer w15: U3.3 135,5505 100,5540 R1.1 R3.2
NetC7_2: C7.2 R4.1 U1.1 | length 236.6
  Top Layer w15: C7.2 871.61,6818.39 887.64,6802.36 U1.1
NetC8_1: C8.1 R5.1 R6.2 U3.2 | length 602.2
  Top Layer w15: U3.2 155,5555 145,5565 145,5645 185,5685 330,5685 340,5695 R6.2 495,5752.6 R5.1
NetC8_2: C8.2 R5.2 U2.8 U3.1 | length 1514.3
  Top Layer w10: U2.8 v1(1009.88,5479.88)
  Top Layer w15: U3.1 227.64,5622.64 255,5650 375,5650 415,5690 545,5690 v1(565,5710) 565,5815 551.61,5828.39 C8.2 ; v1(600,5445) 690,5355 v1(975,5355)
  Bottom Layer w15: v1(565,5710) 600,5675 v1(600,5445) ; v1(975,5355) 1009.88,5389.88 v1(1009.88,5479.88)
NetC15_2: C15.2 R8.1 U1.7 | length 198.9
  Top Layer w15: U1.7 1172.6,6705 R8.1 1192.6,6814.02 C15.2
NetC18_1: C18.1 C20.1 R19.2 R21.1 R24.1 U7.2 | length 1483.4
  Top Layer w15: R24.1 1757.4,3275 ; R21.1 1757.4,3275 ; U7.2 1785,3125 1757.4,3152.6 1757.4,3275 ; C20.1 2095,3855 2037.6,3797.6 R19.2 1870,3360 1845,3335 1845,3275 1757.4,3275
NetC18_2: C18.2 C20.2 R16.2 | length 2279.4
  Top Layer w15: C18.2 v1(1980,3275) R16.2
  Bottom Layer w15: C20.2@320,3855 570,3855 850,3855 1070,3855 1240,3855 1370,3855 1490,3855 1620,3855 1855,3855 1980,3730 v1(1980,3275)
NetC19_2: C19.2 R15.1 R18.2 R27.1 U6.2 | length 677.3
  Top Layer w15: R15.1 R27.1 R18.2 ; C19.2@1057.6,3349.02 R18.2 ; U6.2 1095,3125 1057.6,3162.4 R18.2
NetC23_1: C23.1 C29.1 R21.2 | length 1453.8
  Top Layer w15: C29.1 1682.6,4572.4 R21.2 C23.1
NetC25_2: C25.2 U4.5 | length 146
  Top Layer w15: U4.5 v1(430,3025)
  Bottom Layer w15: C25.2 v1@428.39,3023.39
NetC32_2: C32.2 U8.5 | length 146
  Top Layer w15: U8.5 v1(850,3025)
  Bottom Layer w15: C32.2 v1@848.39,3023.39
NetC33_1: C33.1 R28.1 | length 125
  Top Layer w25: C33.1 R28.1
NetC33_2: C33.2 U5.5 | length 223.2
  Top Layer w25: U5.5 2350,334.88 C33.2
NetC34_2: C34.2 R23.1 | length 885
  Bottom Layer w25: C34.2@2600,3555 2600,3685 2600,3805 2600,3935 2600,4105 R23.1
NetC37_2: C37.2 R30.1 R35.1 U7.3 | length 319.6
  Top Layer w15: C37.2@1590.98,3022.4 R30.1 R35.1 1755,3050 1780,3075 U7.3
NetC38_2: C38.2 U6.5 | length 146
  Top Layer w15: U6.5 v1(1525,3025)
  Bottom Layer w15: C38.2 v1@1523.39,3023.39
NetC39_2: C39.2 U7.5 | length 146
  Top Layer w15: U7.5 v1(2150,3025)
  Bottom Layer w15: C39.2 v1@2148.39,3023.39
NetC42_2: C42.2 R17.1 R29.1 R32.2 U6.3 | length 395.9
  Top Layer w15: R17.1 990,3007.4 1149.02,3007.4 1149.02,3059.02 1165,3075 U6.3
NetC44_1: C44.1 R37.2 | length 319.2
  Top Layer w25: C44.1 2515,1030 R37.2@2615,1030
NetC45_1: C45.1 R38.2 | length 821.6
  Bottom Layer w25: R38.2 2220,2310 C45.1
NetC46_1: C46.1 C47.1 R35.2 R40.2 | length 2433.3
  Top Layer w15: R35.2 1797.4,2947.6 v1(1820,2925) ; R40.2 1860.98,4376.61 C46.1 2193.39,4376.61 C47.1
  Bottom Layer w15: v1(1820,2925) 1910,2835 2160,2835 2205,2880 2205,3360 2110,3455 2110,4260 C47.1
NetC49_1: C49.1 R40.1 R41.2 TP4.1 U9.6 | length 1403.3
  Top Layer w15: R41.2@1757.4,4680 TP4.1 ; R40.1 1860,4645 TP4.1 ; U9.6 2060,4950 ; C49.1 2125,5315 2125,5015 2060,4950 ; TP4.1 1985,4680 2085,4780 2085,4925 2060,4950
NetC49_2: C49.2 R45.1 U9.2 | length 777.5
  Top Layer w15: R45.1 1435,5455 1485,5405 1615,5405 1615,5040 1655,5000 U9.2
NetC50_2: C50.2 R42.1 U10.2 | length 206.5
  Top Layer w10: C50.2 1398.7,5720.32 U10.2
  Top Layer w15: R42.1@1302.4,5775 1363.39,5714.02 C50.2
NetC51_1: C51.1 R41.1 R44.1 R45.2 | length 1028.8
  Top Layer w15: R44.1 1312.4,5287.6 C51.1 1390,5010 1647.6,4752.4 R41.1
NetD2_1: D2.1 U2.7 | length 221.9
  Top Layer w10: U2.7 947.8,5417.2 955,5410 1021.93,5410 D2.1
NetD3_2: D3.2 U2.4 | length 106.5
  Top Layer w10: D3.2 806.81,5590.12 U2.4
NetD12_3: D12.3 R46.2 R47.2 U10.10 | length 434.5
  Top Layer w10: U10.10 1640,5740 1720,5820 R46.2
  Bottom Layer w10: D12.3 1694.29,5880.71 1731.46,5843.54 1749.39,5825.61 ccw(c1775,5851.21) R46.2@1775,5815
NetD13_1: D13.1 R50.2 R51.2 U10.9 | length 567.5
  Top Layer w10: U10.9 1650.32,5720.32 1690,5760 1740,5760 1835,5665 R50.2
  Bottom Layer w10: D13.1 1841.29,5647.89 R51.2 1850.4,5655 R50.2@1935,5655
NetFR1_2: FR1.2 R3.1 | length 433.2
  Top Layer w15: R3.1@265,5832.4 265,5960 425,6120 FR1.2@504.29,6120
NetFR2_2: FR2.2 R6.1 | length 323
  Top Layer w15: R6.1 345,5832.4 345,5960 415,6030 FR2.2@504.29,6030
NetQ1_1: Q1.1 Q1.2 Q3.3 | length 141.2
  Bottom Layer w15: Q1.2 2775,735.71 ; Q3.3 2775,735.71 ; Q1.1 2775,735.71
NetQ2_3: Q2.3 Q4.1 Q4.2 | length 141.2
  Bottom Layer w15: Q4.1 2630,669.29 ; Q2.3 2630,669.29 ; Q4.2 2630,669.29
NetQ3_1: Q3.1 Q3.2 Q4.3 R26.1 R33.1 R37.1 U5.1 | length 2193.7
  Top Layer w15: R26.1 1617.6,347.6 1895,625 2580,625 2630,575 R37.1
  Bottom Layer w15: R37.1 Q4.3 Q3.1
  Bottom Layer w25: R37.1 2750,430 ; U5.1 2750,430 ; R33.1 2750,430
NetR2_2: R2.2 U1.3 | length 101.4
  Top Layer w15: R2.2 807.4,6655 U1.3
NetR7_1: R7.1 R10.1 R13.2 U3.5 | length 715.7
  Top Layer w15: R10.1 427.13,5380 432.36,5385.24 U3.5 ; v1(437.6,5317.6) R13.2 ; v1(525,5625) 540,5625 625,5710 R7.1
  Bottom Layer w15: v1(437.6,5317.6) 525,5405 v1(525,5625)
NetR9_2: R9.2 U1.5 | length 77.1
  Top Layer w15: U1.5 1092.36,6535.04 R9.2
NetR10_2: R10.2 R11.2 | length 243.4
  Top Layer w15: R10.2 292.6,5272.4 325,5240 R11.2
NetR12_1: R12.1 R15.2 R17.2 U4.6 | length 1499.8
  Top Layer w15: R12.1 235,3265 255,3245 255,3080 260,3075 U4.6 v1(445,3075) ; v1(705,3350) R15.2 ; R17.2 922.6,2920 v1(985,2920)
  Bottom Layer w15: v1(445,3075) 705,3075 ; v1(705,3350) 705,3075 ; v1(985,2920) 985,3005 915,3075 705,3075
NetR12_2: R12.2 U4.2 | length 251.8
  Top Layer w15: R12.2 100,3265 75,3240 75,3140 90,3125 U4.2
NetR20_2: R20.2 U5.9 U5.10 | length 490.6
  Top Layer w25: U5.10 1900,140 ; U5.9 1900,140 ; R20.2 1950,360 1900,310 1900,140
NetR27_2: R27.2 R29.2 R39.1 U8.6 | length 708.7
  Top Layer w15: R39.1 675,3265 ; R27.2 675,3265 ; R29.2 977.4,3075 U8.6 695,3075 675,3095 675,3265
NetR28_2: R28.2 U5.4 | length 237.7
  Top Layer w25: U5.4 2450,250 2500,300 2500,349.88 R28.2
NetR39_2: R39.2 U8.2 | length 210.7
  Top Layer w15: R39.2 497.6,3132.4 505,3125 U8.2
NetR51_1: R51.1 U10.7 | length 175.6
  Top Layer w10: U10.7 1683.05,5680.94 v1(1707,5657)
  Bottom Layer w10: v1(1707,5657) 1773.6,5657 R51.1
NetR53_2: R53.2 TP5.1 U10.5 | length 1786
  Top Layer w10: v1(1435,5600) 1440,5605 U10.5
  Top Layer w15: R53.2 1247.4,7087.6 1395,6940 TP5.1@1395,5870
  Bottom Layer w15: TP5.1 1395,5640 v1(1435,5600)
NetU2_2: U2.2 U3.6 U3.7 | length 813.8
  Top Layer w10: U2.2 947.8,5687.8
  Top Layer w15: U3.6 525,5505 535,5515 535,5560 670,5695 940.59,5695 947.8,5687.8 ; U3.7 525,5555
NHV: P2.1 R52.1 | length 325
  Bottom Layer w25: R52.1 P2.1
NREF: C14.2 P1.6 R9.1 R11.1 | length 3526.9
  Top Layer w15: P1.6 450,7150 450,7055 550,6955 v1(550,6545) 550,6485.12 C14.2 ; v1(650,6550) 670.36,6529.64 1022.24,6529.64 R9.1
  Bottom Layer w15: R11.1 425,5085 400,5060 135.5,5060 70.5,5125 70.5,6355.5 260,6545 v1(550,6545) 645,6545 v1(650,6550)
OFS_N: FR2.1 P1.14 | length 1972.3
  Top Layer w15: FR2.1 655.71,6020 1025.71,6390 1260,6390 1360,6490 1360,6920 1080,7200 P1.14
OFS_P: FR1.1 P1.13 | length 1780.1
  Top Layer w15: FR1.1 675.71,6130 995.71,6450 1250,6450 1325,6525 1325,6895 1120,7100 P1.13
OFSADJ: R44.2 U2.1 | length 471.5
  Top Layer w10: U2.1 973.39,5643.39
  Top Layer w15: 973.39,5643.39 1015,5685 1215,5685 1237.6,5662.4 R44.2
OK: P1.10 R53.1 | length 533.3
  Top Layer w15: P1.10 700,7255 720,7275 R53.1@1170,7275
P: C21.2 C22.2 D9.2 R43.2 R46.1 R48.2 U5.11 U5.12 | length 7324.4
  Bottom Layer w25: R43.2 R48.2 1725,6305 2155,5875 2325,5875 2375,5825 R46.1 ; U5.12 U5.11 ; 1698.23,141.77 C21.2 1641.42,416.81 D9.2 1641.42,941.42 1685,985 1830,985 2375,1530 R46.1@2375,5805
P15: C3.2 C5.2 C6.2 C9.2 C13.2 C17.2 C27.2 C28.2 C43.2 C48.2 D3.1 D4.2 P1.1 R42.2 R48.1 TP6.1 U1.8 U3.8 U4.7 U6.7 U7.7 U8.7 U9.7 | length 2548.1
  Top Layer w15: U4.7 v1(430,3125) ; U3.8 v1(432.36,5642.64) ; v1(715,5410) C3.2 788.54,5461.61 D3.1 ; U8.7 v1(850,3125) ; U1.8 v1(1092.36,6797.36) ; v1(1165,5775) R42.2 ; U6.7 v1(1525,3125) ; U9.7 2045,5000 2060,5015 v1(2060,5140) C48.2 ; U7.7 v1(2150,3125)
  Top Layer w25: D4.2 144.29,6930 144.29,7009.29 235,7100 P1.1
  Bottom Layer w15: C17.2 366.61,3125 v1(430,3125) ; C13.2 432.36,5588.98 v1(432.36,5642.64) ; C43.2 786.61,3125 v1(850,3125) ; C9.2 1092.36,6743.98 v1(1092.36,6797.36) ; C27.2 1461.61,3125 v1(1525,3125) ; C28.2 2086.61,3125 v1(2150,3125)
  Bottom Layer w25: v2(1200,6560) 1200,6620 1280,6700 1660,6700 1725,6765 R48.1
PB: C7.1 P1.7 R4.2 U1.2 | length 629.9
  Top Layer w15: P1.7 600,7015 635,6980 635,6760 653.39,6741.61 C7.1 780.98,6741.61 R4.2 817.6,6705 U1.2
PHV: P2.3 R43.1 | length 325
  Bottom Layer w25: R43.1 P2.3
SB: P1.9 R7.2 | length 1308.7
  Top Layer w15: R7.2 v1(625,5950)
  Bottom Layer w15: v1(625,5950) 625,6270 700,6345 P1.9
T_N: C24.2 J2.2 R14.1 U4.3 | length 3569.2
  Top Layer w15: v1(85,3075) U4.3 ; C24.2@170,776.61 248.39,776.61 ; R14.1 217.6,1012.4 v1(248.39,981.61) 248.39,776.61 ; J2.2@400,580 400,625 248.39,776.61
  Bottom Layer w15: v1@85,3080.41 v1(85,3075) 75,3075 75,2915 200,2790 200,2270 95,2165 95,1345 145,1295 145,1085 v1(248.39,981.61)
  Bottom Layer w25: J2.2@200,580 200,380 400,380 J2.2@400,580
T_P: C31.1 J2.1 R31.2 U8.3 | length 3049.9
  Top Layer w15: J2.1 160,480 95,545 C31.1 145,1141.61 145,1362.89 136.21,1371.68 110.72,1371.68 R31.2 95,1970 400,2275 400,2875 490,2965 490,3050 515,3075 U8.3
TP1: C19.1 C23.2 C29.2 R18.1 R24.2 TP1.1 U6.6 | length 3145.3
  Top Layer w15: C29.2@975,4680 975,3645 TP1.1 ; R18.1@1133.39,3265.98 C19.1@1133.39,3330 ; C19.1 C19.1@1133.39,3330 ; U6.6 1365,3075 1350,3090 1350,3330 ; C23.2@1516.61,3330 1350,3330 ; R24.2@1521.61,3275.98 C23.2 ; C19.1@1133.39,3330 TP1.1 ; TP1.1 1350,3330
  Bottom Layer w15: C29.2@205,4680 425,4680 595,4680 725,4680 845,4680 C29.2@975,4680
TP2: R16.1 R19.1 R26.2 TP2.1 U7.6 | length 3744.9
  Top Layer w15: R26.2 TP2.1 1110,905 1110,1435 1915,2240 1915,2605 2205,2895 2205,3055 2185,3075 ; U7.6 2185,3075 ; R19.1 R16.1 2170,3275 2205,3240 2205,3095 2185,3075
VREF: C10.2 P1.5 R2.1 R11.3 | length 2474.7
  Top Layer w15: P1.5 500,7060 590,6970 590,6640 ; C10.2 615,6375 630,6390 v1(630,6395) 630,6510 590,6550 590,6640 ; R2.1 590,6640
  Bottom Layer w15: R11.3 105,5270 105,5860 630,6385 v1(630,6395)
pads on no net: D12.2 D13.2 J2.3 J2.4 J3.3 J3.4 U2.5 U4.1 U4.8 U5.3 U6.1 U6.8 U7.1 U7.8 U8.1 U8.8 U9.1 U9.5 U9.8 U10.1 U10.3 U10.4

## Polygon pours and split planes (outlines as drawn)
GND on GND1 (split plane): 1375,5800 2275,5800 2275,2500 1450,2500 1450,1925 150,1925 150,1075 1000,1075 1000,700 1275,700 1275,170.1 20.1,170.1 20.1,7479.9 1375,7479.9
P15 on P15 (split plane): 1375,5800 2275,5800 2275,2500 1450,2500 1450,1925 150,1925 150,1075 1000,1075 1000,700 1275,700 1275,170.1 20.1,170.1 20.1,7479.9 1375,7479.9
N15 on N15 (split plane): 1375,5800 2275,5800 2275,2500 1450,2500 1450,1925 150,1925 150,1075 1000,1075 1000,700 1275,700 1275,170.1 20.1,170.1 20.1,7479.9 1375,7479.9
GND on GND2 (split plane): 1375,5800 2275,5800 2275,2500 1450,2500 1450,1925 150,1925 150,1075 1000,1075 1000,700 1275,700 1275,170.1 20.1,170.1 20.1,7479.9 1375,7479.9

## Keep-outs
Keep-Out Layer:
  lines w10: 25,200 25,350 50,350 50,3350 25,3350 25,3500 25,3525 25,3675 50,3675 50,7450 2850,7450 2850,50 1500,50 1500,200 25,200

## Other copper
GND1 (plane layer: these items are gaps in the copper):
  rectangle: 1275,150 1450,700
  rectangle: 1000,700 1550,1075
  rectangle: 150,1075 1450,1925
  rectangle: 1450,1500 2275,2500
  rectangle: 2275,1425 2900,5800
  rectangle: 1375,5800 2900,7500
  rectangle: 1450,0 2900,1500
P15 (plane layer: these items are gaps in the copper):
  rectangle: 1275,150 1450,700
  rectangle: 1000,700 1550,1075
  rectangle: 150,1075 1450,1925
  rectangle: 1450,1500 2275,2500
  rectangle: 2275,1425 2900,5800
  rectangle: 1375,5800 2900,7500
  rectangle: 1450,0 2900,1500
N15 (plane layer: these items are gaps in the copper):
  rectangle: 1450,0 2900,1500
  rectangle: 1375,5800 2900,7500
  rectangle: 2275,1425 2900,5800
  rectangle: 1450,1500 2275,2500
  rectangle: 150,1075 1450,1925
  rectangle: 1000,700 1550,1075
  rectangle: 1275,150 1450,700
GND2 (plane layer: these items are gaps in the copper):
  rectangle: 1450,0 2900,1500
  rectangle: 1375,5800 2900,7500
  rectangle: 2275,1425 2900,5800
  rectangle: 1450,1500 2275,2500
  rectangle: 150,1075 1450,1925
  rectangle: 1000,700 1550,1075
  rectangle: 1275,150 1450,700

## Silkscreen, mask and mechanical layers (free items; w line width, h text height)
Top Overlay:
  rectangle: 765,5940 2094.06,6330
  lines w12: 1500,7360 1500,7480 2100,7480 2100,7360 ; 1700,7360 1700,7480 ; 1900,7360 1900,7480 ; 2500,7360 2500,7480 2700,7480 2700,7360
  lines w15: 1455,6875 1525,6875 ; 1490,6840 1490,6910 ; 2075,6875 2145,6875
  text "D1001203" at 780,6375 h65
  text "rev. 3" at 1335,6375 h65
  text "PZT Driver" at 2760,5325 h100 r90
Mechanical 1:
  the board outline again, w10
Drill Drawing:
  drawing of 177 lines, arcs and shapes, not listed
  text "Hole Tolerance (-)" at 3320,9222.85 h72 r90
  text "Hole Tolerance (+)" at 3320,7889.24 h72 r90
  text "Description" at 3320,7035.48 h72 r90
  text "Template" at 3320,6385.65 h72 r90
  text "c152h81" at 3470,6385.65 h60 r90
  text "c203h152" at 3620,6385.65 h60 r90
  text "c635h330" at 3770,6385.65 h60 r90
  text "(Mixed)" at 3920,6385.65 h60 r90
  text "(Mixed)" at 4070,6385.65 h60 r90
  text "c305h203" at 4220,6385.65 h60 r90
  text "v127h71" at 4370,6385.65 h60 r90
  text "c254h158" at 4520,6385.65 h60 r90
  text "c165h84" at 4670,6385.65 h60 r90
  text "c216h165" at 4820,6385.65 h60 r90
  text "(Mixed)" at 4970,6385.65 h60 r90
  text "c190h122" at 5120,6385.65 h60 r90
  text "c140h85" at 5270,6385.65 h60 r90
  text "c165h97" at 5420,6385.65 h60 r90
  text "v89h38" at 5570,6385.65 h60 r90
  text "Pad Shape" at 3320,5639.85 h72 r90
  text "Rounded" at 3470,5639.85 h60 r90
  text "Rounded" at 3620,5639.85 h60 r90
  text "Rounded" at 3770,5639.85 h60 r90
  text "(Mixed)" at 3920,5639.85 h60 r90
  text "(Mixed)" at 4070,5639.85 h60 r90
  text "Rounded" at 4220,5639.85 h60 r90
  text "Rounded" at 4370,5639.85 h60 r90
  text "Rounded" at 4520,5639.85 h60 r90
  text "Rounded" at 4670,5639.85 h60 r90
  text "Rounded" at 4820,5639.85 h60 r90
  text "(Mixed)" at 4970,5639.85 h60 r90
  text "Rounded" at 5120,5639.85 h60 r90
  text "Rounded" at 5270,5639.85 h60 r90
  text "Rounded" at 5420,5639.85 h60 r90
  text "Rounded" at 5570,5639.85 h60 r90
  text "Via/Pad" at 3320,5050 h72 r90
  text "Pad" at 3470,5050 h60 r90
  text "Pad" at 3620,5050 h60 r90
  text "Pad" at 3770,5050 h60 r90
  text "Pad" at 3920,5050 h60 r90
  text "Pad" at 4070,5050 h60 r90
  text "Pad" at 4220,5050 h60 r90
  text "Via" at 4370,5050 h60 r90
  text "Pad" at 4520,5050 h60 r90
  text "Pad" at 4670,5050 h60 r90
  text "Pad" at 4820,5050 h60 r90
  text "Pad" at 4970,5050 h60 r90
  text "Pad" at 5120,5050 h60 r90
  text "Pad" at 5270,5050 h60 r90
  text "Pad" at 5420,5050 h60 r90
  text "Via" at 5570,5050 h60 r90
  text "Drill Layer Pair" at 3320,3550.45 h72 r90
  text "Top Layer - Bottom Layer" at 3470,3550.45 h60 r90
  text "Top Layer - Bottom Layer" at 3620,3550.45 h60 r90
  text "Top Layer - Bottom Layer" at 3770,3550.45 h60 r90
  text "Top Layer - Bottom Layer" at 3920,3550.45 h60 r90
  text "Top Layer - Bottom Layer" at 4070,3550.45 h60 r90
  text "Top Layer - Bottom Layer" at 4220,3550.45 h60 r90
  text "Top Layer - Bottom Layer" at 4370,3550.45 h60 r90
  text "Top Layer - Bottom Layer" at 4520,3550.45 h60 r90
  text "Top Layer - Bottom Layer" at 4670,3550.45 h60 r90
  text "Top Layer - Bottom Layer" at 4820,3550.45 h60 r90
  text "Top Layer - Bottom Layer" at 4970,3550.45 h60 r90
  text "Top Layer - Bottom Layer" at 5120,3550.45 h60 r90
  text "Top Layer - Bottom Layer" at 5270,3550.45 h60 r90
  text "Top Layer - Bottom Layer" at 5420,3550.45 h60 r90
  text "Top Layer - Bottom Layer" at 5570,3550.45 h60 r90
  text "Hole Type" at 3320,2816.65 h72 r90
  text "Round" at 3470,2816.65 h60 r90
  text "Round" at 3620,2816.65 h60 r90
  text "Round" at 3770,2816.65 h60 r90
  text "Round" at 3920,2816.65 h60 r90
  text "Round" at 4070,2816.65 h60 r90
  text "Round" at 4220,2816.65 h60 r90
  text "Round" at 4370,2816.65 h60 r90
  text "Round" at 4520,2816.65 h60 r90
  text "Round" at 4670,2816.65 h60 r90
  text "Round" at 4820,2816.65 h60 r90
  text "Round" at 4970,2816.65 h60 r90
  text "Round" at 5120,2816.65 h60 r90
  text "Round" at 5270,2816.65 h60 r90
  text "Round" at 5420,2816.65 h60 r90
  text "Round" at 5570,2816.65 h60 r90
  text "Plated" at 3320,2310.77 h72 r90
  text "PTH" at 3470,2310.77 h60 r90
  text "PTH" at 3620,2310.77 h60 r90
  text "PTH" at 3770,2310.77 h60 r90
  text "PTH" at 3920,2310.77 h60 r90
  text "PTH" at 4070,2310.77 h60 r90
  text "PTH" at 4220,2310.77 h60 r90
  text "PTH" at 4370,2310.77 h60 r90
  text "PTH" at 4520,2310.77 h60 r90
  text "PTH" at 4670,2310.77 h60 r90
  text "PTH" at 4820,2310.77 h60 r90
  text "PTH" at 4970,2310.77 h60 r90
  text "PTH" at 5120,2310.77 h60 r90
  text "PTH" at 5270,2310.77 h60 r90
  text "PTH" at 5420,2310.77 h60 r90
  text "PTH" at 5570,2310.77 h60 r90
  text "Hole Size" at 3320,1161.11 h72 r90
  text "32.00mil (0.813mm)" at 3470,1161.11 h60 r90
  text "60.00mil (1.524mm)" at 3620,1161.11 h60 r90
  text "130.00mil (3.302mm)" at 3770,1161.11 h60 r90
  text "35.43mil (0.900mm)" at 3920,1161.11 h60 r90
  text "62.00mil (1.575mm)" at 4070,1161.11 h60 r90
  text "80.00mil (2.032mm)" at 4220,1161.11 h60 r90
  text "28.00mil (0.711mm)" at 4370,1161.11 h60 r90
  text "62.21mil (1.580mm)" at 4520,1161.11 h60 r90
  text "33.00mil (0.838mm)" at 4670,1161.11 h60 r90
  text "65.00mil (1.651mm)" at 4820,1161.11 h60 r90
  text "39.37mil (1.000mm)" at 4970,1161.11 h60 r90
  text "48.00mil (1.219mm)" at 5120,1161.11 h60 r90
  text "33.47mil (0.850mm)" at 5270,1161.11 h60 r90
  text "38.00mil (0.965mm)" at 5420,1161.11 h60 r90
  text "15.00mil (0.381mm)" at 5570,1161.11 h60 r90
  text "Count" at 3320,571.26 h72 r90
  text "2" at 3470,571.26 h60 r90
  text "2" at 3620,571.26 h60 r90
  text "2" at 3770,571.26 h60 r90
  text "3" at 3920,571.26 h60 r90
  text "3" at 4070,571.26 h60 r90
  text "4" at 4220,571.26 h60 r90
  text "7" at 4370,571.26 h60 r90
  text "9" at 4520,571.26 h60 r90
  text "12" at 4670,571.26 h60 r90
  text "13" at 4820,571.26 h60 r90
  text "14" at 4970,571.26 h60 r90
  text "22" at 5120,571.26 h60 r90
  text "26" at 5270,571.26 h60 r90
  text "29" at 5420,571.26 h60 r90
  text "71" at 5570,571.26 h60 r90
  text "219 Total" at 5720,571.26 h60 r90
  text "Symbol" at 3320,65.39 h72 r90
  text "A" at 3629.99,36.3 h66.67 r90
